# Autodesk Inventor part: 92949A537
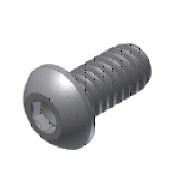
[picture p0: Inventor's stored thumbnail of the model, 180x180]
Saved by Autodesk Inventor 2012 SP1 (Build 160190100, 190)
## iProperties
Created: 2012-02
Part Number: 92949A537
Material: Default
Description: 18-8 SS Button Head Socket Cap Screw 1/4"-20 Thread, 1/2" Length
Document SubType Name: Modeling
Designer: LACO
Language: en-US
Size Designation: 92949A537-Default
Categories: <MemberInstance><Categories><Category DisplayName="screw" InternalName="7a1e6ee9-cc68-45f8-999b-cbba04488bc6" Mnemonic="SCREW"><Category DisplayName="button-hea
Density: 1 g/cm^3
Mass: 0.561118 g
Surface Area: 6.06239 cm^2
Volume: 0.561118 cm^3
Translation Standard: STEP AP203
FileName: 92949A537.step
PreProcessor: SolidWorks 2006233
PostProcessor: Build: 190, Release: 2012 SP1 - Date: Mon 08/08/2011
Sent Units: inch
Uncertainty: 1e-05
IsCustomPart: 0
Author: LACO
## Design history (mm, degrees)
node "92949A5371"
node "NONE"
node "Base1"
